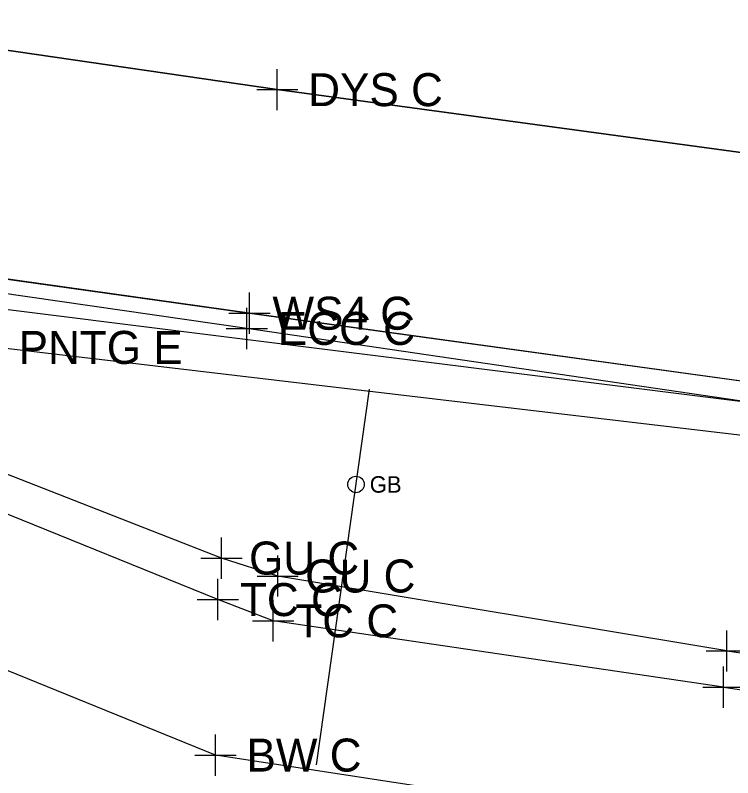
# Model space of a CAD drawing. Extents: x 1363693 to 1365209, y 422201 to 424153.
# Drawn here: x 1363758.91 to 1363793.74, y 423122.33 to 423159.32 of the extents above; entities that cross this region are included whole.
import ezdxf

# ---------------------------------------------------------------- set-up
doc = ezdxf.new("R2010")
doc.units = 0
for name, color, linetype in [('BASELINE-CL-RW', 7, 'Continuous'), ('O-ALGN-BASELINE-WERK-CL-RW', 7, 'Continuous'), ('O-ALGN-TEXT-BASELINE-WERK-CL-RW', 7, 'Continuous'), ('OWNERS', 7, 'Continuous'), ('PM_X_Channelizing_Line', 7, 'Continuous'), ('PM_X_Edge_Line', 7, 'Continuous'), ('SV_X_Original_Ground', 7, 'Continuous'), ('SV_X_Random_Point', 7, 'Continuous'), ('SV_X_Shot_Marker', 7, 'Continuous'), ('UT_X_Gas', 7, 'Continuous'), ('UT_X_Gas_Cells', 7, 'Continuous'), ('UT_X_Gas_Text', 7, 'Continuous'), ('UT_X_Telecom_FO', 7, 'Continuous')]:
    doc.layers.add(name, color=color, linetype=linetype)

msp = doc.modelspace()

# ---------------------------------------------------------------- linework, layer by layer
at = {"layer": 'BASELINE-CL-RW'}
for p, q in [((1363768.746, 423130.97), (1363744.85, 423140.656)), ((1363771.435, 423129.937), (1363768.746, 423130.97)), ((1363793.28, 423126.723), (1363771.435, 423129.937))]:
    msp.add_line(p, q, dxfattribs=at)
msp.add_lwpolyline([(1363793.28, 423126.723), (1363811.112, 423124.134), (1363815.327, 423123.148), (1363815.327, 423123.148), (1363817.944, 423122.102), (1363817.944, 423122.102), (1363820.858, 423120.543), (1363820.858, 423120.543), (1363823.399, 423119.04), (1363823.399, 423119.04), (1363825.331, 423117.535), (1363825.331, 423117.535), (1363828.012, 423114.591), (1363828.012, 423114.591), (1363830.96, 423111.021)], dxfattribs=at)
at = {"layer": 'O-ALGN-BASELINE-WERK-CL-RW'}
for p, q in [((1363771.631, 423155.711), (1363746.859, 423159.322)), ((1363796.066, 423152.4), (1363771.631, 423155.711))]:
    msp.add_line(p, q, dxfattribs=at)
at = {"layer": 'O-ALGN-TEXT-BASELINE-WERK-CL-RW'}
for p, q in [((1363768.636, 423123.426), (1363743.787, 423133.516)), ((1363792.518, 423119.771), (1363768.636, 423123.426))]:
    msp.add_line(p, q, dxfattribs=at)
at = {"layer": 'OWNERS'}
for p, q in [((1363770.157, 423144.126), (1363745.448, 423147.682)), ((1363794.956, 423140.485), (1363770.157, 423144.126)), ((1363768.922, 423132.985), (1363744.946, 423142.333)), ((1363771.65, 423132.114), (1363768.922, 423132.985)), ((1363793.444, 423128.476), (1363771.65, 423132.114))]:
    msp.add_line(p, q, dxfattribs=at)
msp.add_lwpolyline([(1363793.444, 423128.476), (1363811.4, 423125.917), (1363815.545, 423124.837), (1363815.545, 423124.837), (1363818.169, 423123.827), (1363818.169, 423123.827), (1363821.556, 423122.157), (1363821.556, 423122.157), (1363824.673, 423120.433), (1363824.673, 423120.433), (1363825.864, 423119.619), (1363826.928, 423118.645), (1363826.928, 423118.645), (1363828.508, 423116.831), (1363829.93, 423114.891), (1363829.93, 423114.891), (1363830.96, 423111.021)], dxfattribs=at)
at = {"layer": 'PM_X_Channelizing_Line'}
for p, q in [((1363746.859, 423159.322), (1363771.631, 423155.711)), ((1363771.631, 423155.711), (1363796.066, 423152.4)), ((1363745.562, 423148.337), (1363770.278, 423144.864)), ((1363770.278, 423144.864), (1363795.104, 423141.445))]:
    msp.add_line(p, q, dxfattribs=at)
at = {"layer": 'PM_X_Edge_Line'}
msp.add_lwpolyline([(1363795.104, 423141.445), (1363770.278, 423144.864), (1363745.562, 423148.337), (1363720.729, 423151.997), (1363716.348, 423152.621), (1363695.969, 423155.534)], dxfattribs=at)
at = {"layer": 'SV_X_Original_Ground'}
for p, q in [((1363771.631, 423154.711), (1363771.631, 423156.711)), ((1363770.631, 423155.711), (1363772.631, 423155.711)), ((1363770.278, 423143.864), (1363770.278, 423145.864)), ((1363769.278, 423144.864), (1363771.278, 423144.864))]:
    msp.add_line(p, q, dxfattribs=at)
at = {"layer": 'SV_X_Shot_Marker'}
for p, q in [((1363770.157, 423143.126), (1363770.157, 423145.126)), ((1363769.157, 423144.126), (1363771.157, 423144.126)), ((1363768.922, 423131.985), (1363768.922, 423133.985)), ((1363767.922, 423132.985), (1363769.922, 423132.985)), ((1363771.65, 423131.114), (1363771.65, 423133.114)), ((1363768.746, 423129.97), (1363768.746, 423131.97)), ((1363770.65, 423132.114), (1363772.65, 423132.114)), ((1363767.746, 423130.97), (1363769.746, 423130.97)), ((1363771.435, 423128.937), (1363771.435, 423130.937)), ((1363770.435, 423129.937), (1363772.435, 423129.937)), ((1363793.444, 423127.476), (1363793.444, 423129.476)), ((1363792.444, 423128.476), (1363794.444, 423128.476)), ((1363793.28, 423125.723), (1363793.28, 423127.723)), ((1363792.28, 423126.723), (1363794.28, 423126.723)), ((1363768.636, 423122.426), (1363768.636, 423124.426)), ((1363767.636, 423123.426), (1363769.636, 423123.426))]:
    msp.add_line(p, q, dxfattribs=at)
at = {"layer": 'UT_X_Gas'}
msp.add_line((1363776.097, 423141.182), (1363773.522, 423122.949), dxfattribs=at)
msp.add_lwpolyline([(1363697.823, 423150.328), (1364024.78, 423111.733), (1364079.651, 423106.56), (1364321.815, 423073.856), (1364574.009, 423047.674), (1364582.932, 423046.282), (1364615.757, 423042.884), (1364684.796, 423035.164)], dxfattribs=at)
at = {"layer": 'UT_X_Gas_Cells'}
msp.add_circle((1363775.45, 423136.557), 0.4, dxfattribs=at)
at = {"layer": 'UT_X_Telecom_FO'}
msp.add_line((1363696.706, 423152.79), (1363858.609, 423132.532), dxfattribs=at)

# ---------------------------------------------------------------- texts
at = {"layer": 'SV_X_Original_Ground'}
for s, p in [('DYS C', (1363773.131, 423154.911)), ('WS4 C', (1363771.397, 423144.064))]:
    msp.add_text(s, height=1.6, dxfattribs=at).set_placement(p)
at = {"layer": 'SV_X_Random_Point'}
msp.add_text('PNTG E', height=1.6, dxfattribs=at).set_placement((1363759.075, 423142.405))
at = {"layer": 'SV_X_Shot_Marker'}
for s, p in [('ECC C', (1363771.657, 423143.326)), ('GU C', (1363770.258, 423132.185)), ('GU C', (1363772.986, 423131.314)), ('TC C', (1363769.818, 423130.17)), ('TC C', (1363772.506, 423129.137)), ('BW C', (1363770.136, 423122.626))]:
    msp.add_text(s, height=1.6, dxfattribs=at).set_placement(p)
at = {"layer": 'UT_X_Gas_Text'}
msp.add_text('GB', height=0.8, dxfattribs=at).set_placement((1363776.118, 423136.157))

doc.saveas('drawing.dxf')
